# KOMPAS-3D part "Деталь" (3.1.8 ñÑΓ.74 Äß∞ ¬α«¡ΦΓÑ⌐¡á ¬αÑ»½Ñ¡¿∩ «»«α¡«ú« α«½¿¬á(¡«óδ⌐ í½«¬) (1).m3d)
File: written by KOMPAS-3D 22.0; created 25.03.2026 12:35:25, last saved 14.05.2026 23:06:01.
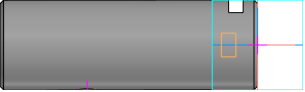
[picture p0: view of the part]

Document properties: Автор: TMK; Полное имя файла: E:\test_kompas\all_v20\3.1.8 дет.74 Ось кронштейна крепления опорного ролика(новый блок) (1).m3d; Организация: TMK

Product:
- Part/product: Деталь
    Масса: 2.046242

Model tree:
1. Эскиз:1
2. Элемент выдавливания:1
     Расстояние 2 = 142
3. Фаска:1
     Угол = 45; Длина 1 = 2; Длина 2 = 2
4. Эскиз:2
5. Отверстие:2  (with: Элемент выдавливания:1)
     Глубина выреза = 99.5; Диаметр отверстия = 11.4448; Угол конуса дна = 118; Диаметр цековки = 23; Глубина цековки = 12
6. G 1/4  (with: Отверстие:2)
     Длина резьбы = 20; Шаг резьбы = 1.337; Номинальный диаметр резьбы = 13.157
7. Фаска:2
     Угол = 45; Длина 1 = 1.6; Длина 2 = 1.6
8. Смещенная плоскость:2
     Расстояние = 25
9. Эскиз:4
10. Отверстие:3
     Глубина выреза = 30.5; Диаметр отверстия = 11.5; Угол конуса дна = 118; Расстояние 2 = -94
11. Смещенная плоскость:3
     Расстояние = 25
12. Эскиз:5
13. Элемент выдавливания:3
     Расстояние 2 = 50

Expressions: cil2_6357-81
